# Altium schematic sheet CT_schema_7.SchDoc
size 274 x 160 mm
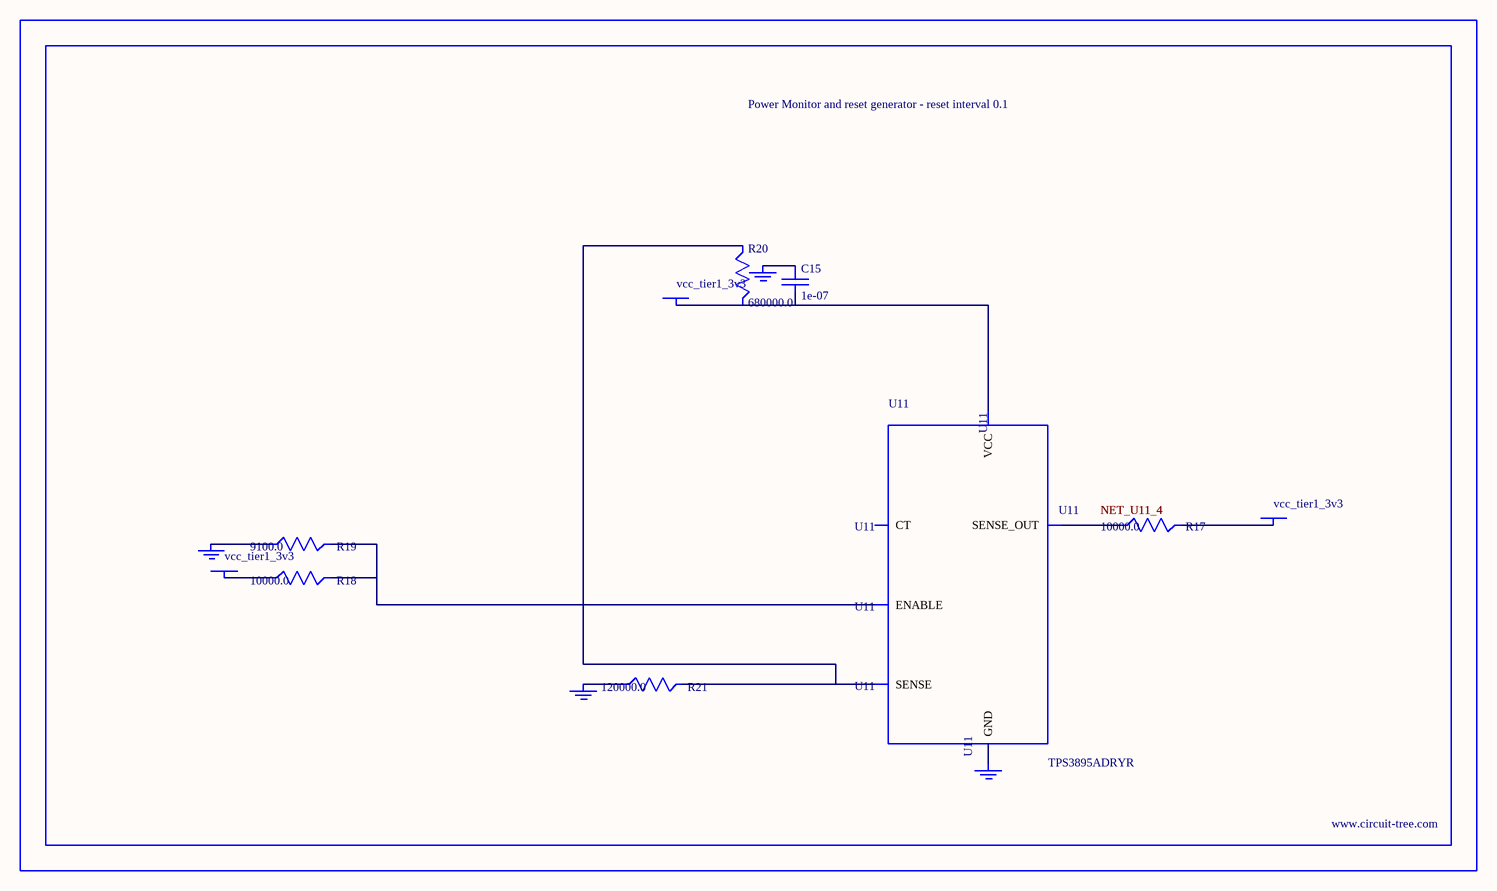
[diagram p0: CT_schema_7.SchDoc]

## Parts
BORDER6  (no value)
C15  1e-07  [C0402]
GND_INSTANCE_6_0  (no value)
GND_INSTANCE_6_1  (no value)
GND_INSTANCE_6_2  (no value)
GND_INSTANCE_6_3  (no value)
POWER_INSTANCE_6_0  vcc_tier1_3v3
POWER_INSTANCE_6_1  vcc_tier1_3v3
POWER_INSTANCE_6_2  vcc_tier1_3v3
R17  10000.0  [R0603]
R18  10000.0  [R0603]
R19  9100.0  [R0603]
R20  680000.0  [R0603]
R21  120000.0  [R0603]
U11  TPS3895ADRYR  [SON-6]

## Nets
NetC15_1: C15.1 GND_INSTANCE_6_2.0(GND)
NetC15_2: C15.2 POWER_INSTANCE_6_2.0(PWR) R20.2 U11.6(VCC)
NetGND_INSTANCE_6_0_0: GND_INSTANCE_6_0.0(GND) R19.1
NetGND_INSTANCE_6_1_0: GND_INSTANCE_6_1.0(GND) R21.1
NetGND_INSTANCE_6_3_0: GND_INSTANCE_6_3.0(GND) U11.2(GND)
NetPOWER_INSTANCE_6_0_0: POWER_INSTANCE_6_0.0(PWR) R18.1
NetPOWER_INSTANCE_6_1_0: POWER_INSTANCE_6_1.0(PWR) R17.2
NetR17_1: R17.1 U11.4(SENSE_OUT)
NetR18_2: R18.2 R19.2 U11.1(ENABLE)
NetR20_1: R20.1 R21.2 U11.3(SENSE)

Not connected (* = marked no-connect by the designer): U11 5(CT)

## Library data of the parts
BORDER6 = BORDER_PAGE6
C15 = C0402C104K3RACTU
GND_INSTANCE_6_0-GND_INSTANCE_6_3 = GND
POWER_INSTANCE_6_0-POWER_INSTANCE_6_2 = PWR
R17 R18 = RC0603JR-0710KL
R19 = RC0603JR-079K1L
R20 = RC0603JR-07680KL
R21 = RC0603JR-07120KL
